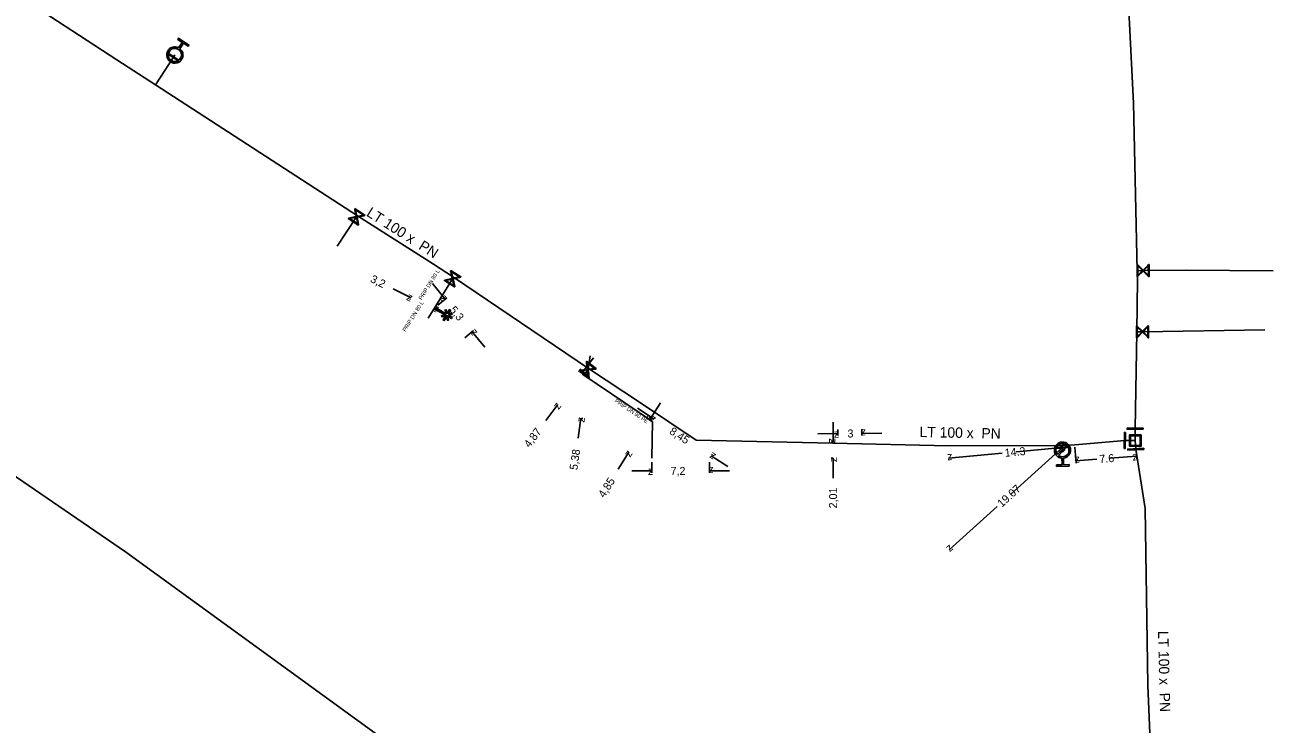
# Model space of a CAD drawing. Extents: x -643544 to -637295, y -1119190 to -1111715.
# Drawn here: x -641787.1 to -641631.1, y -1115673.3 to -1115585.9 of the extents above; entities that cross this region are included whole.
import ezdxf

# ---------------------------------------------------------------- set-up
doc = ezdxf.new("R2010")
doc.units = 0
for name, color, linetype in [('Default', 7, 'Continuous'), ('VP Hydrant', 7, 'Continuous'), ('VP Kótování', 7, 'Continuous'), ('VP Popis přípojky', 7, 'Continuous'), ('VP Přípojka', 7, 'Continuous'), ('VP Změna materiálu', 7, 'Continuous'), ('VP Řad', 7, 'Continuous'), ('VP Řad - popis', 7, 'Continuous'), ('VP Šachta', 7, 'Continuous'), ('VP Šoupě', 7, 'Continuous')]:
    doc.layers.add(name, color=color, linetype=linetype)

msp = doc.modelspace()

# ---------------------------------------------------------------- linework, layer by layer
at = {"layer": 'Default'}
for points in [[(-641767.77, -1115588.87), (-641767.48, -1115589.09), (-641767.41, -1115589.45), (-641767.33, -1115589.85), (-641767.56, -1115590.2), (-641767.78, -1115590.55), (-641768.19, -1115590.63), (-641768.59, -1115590.71), (-641768.94, -1115590.48), (-641769.29, -1115590.26), (-641769.37, -1115589.85), (-641769.45, -1115589.45), (-641769.23, -1115589.1), (-641769, -1115588.75), (-641768.59, -1115588.67), (-641768.23, -1115588.59), (-641767.92, -1115588.77)], [(-641767.94, -1115588.97), (-641768.23, -1115588.78), (-641768.55, -1115588.85), (-641768.88, -1115588.92), (-641769.07, -1115589.2), (-641769.25, -1115589.48), (-641769.19, -1115589.81), (-641769.12, -1115590.14), (-641768.84, -1115590.33), (-641768.56, -1115590.51), (-641768.23, -1115590.44), (-641767.9, -1115590.38), (-641767.71, -1115590.09), (-641767.53, -1115589.81), (-641767.59, -1115589.48), (-641767.66, -1115589.15), (-641767.94, -1115588.97)], [(-641657.52, -1115640.05), (-641657.88, -1115640.04), (-641658.14, -1115639.78), (-641658.44, -1115639.5), (-641658.45, -1115639.08), (-641658.46, -1115638.67), (-641658.18, -1115638.37), (-641657.89, -1115638.07), (-641657.48, -1115638.06), (-641657.07, -1115638.05), (-641656.76, -1115638.33), (-641656.46, -1115638.61), (-641656.45, -1115639.03), (-641656.44, -1115639.44), (-641656.72, -1115639.74), (-641656.98, -1115640.01), (-641657.33, -1115640.05)], [(-641656.96, -1115638.41), (-641657.18, -1115638.24), (-641657.47, -1115638.25), (-641657.81, -1115638.26), (-641658.04, -1115638.5), (-641658.27, -1115638.74), (-641658.26, -1115639.08), (-641658.25, -1115639.37), (-641658.08, -1115639.58)], [(-641657.94, -1115639.71), (-641657.72, -1115639.88), (-641657.43, -1115639.87), (-641657.09, -1115639.86), (-641656.86, -1115639.62), (-641656.63, -1115639.37), (-641656.64, -1115639.04), (-641656.65, -1115638.74), (-641656.83, -1115638.53)]]:
    msp.add_open_spline(points, degree=3, dxfattribs=at)
at = {"layer": 'VP Hydrant'}
for points in [[(-641767.92, -1115588.77), (-641767.47, -1115588.08), (-641768.04, -1115587.7), (-641767.94, -1115587.55), (-641766.64, -1115588.41), (-641766.74, -1115588.56), (-641767.31, -1115588.18), (-641767.77, -1115588.87)], [(-641658.08, -1115639.58), (-641656.96, -1115638.41)], [(-641656.83, -1115638.53), (-641657.94, -1115639.71)], [(-641657.33, -1115640.05), (-641657.31, -1115640.87), (-641656.62, -1115640.85), (-641656.62, -1115641.04), (-641658.18, -1115641.08), (-641658.18, -1115640.89), (-641657.5, -1115640.87), (-641657.52, -1115640.05)]]:
    msp.add_lwpolyline(points, dxfattribs=at)
at = {"layer": 'VP Kótování'}
for points in [[(-641741.11, -1115618.88), (-641738.87, -1115620)], [(-641736.19, -1115618.23), (-641734.61, -1115620.16)], [(-641738.99, -1115620.25), (-641738.98, -1115620.22)], [(-641735.52, -1115620.91), (-641734.41, -1115620)], [(-641736.13, -1115621.67), (-641736.11, -1115621.64)], [(-641733.76, -1115622.53), (-641736, -1115621.42)], [(-641732.16, -1115625.01), (-641731.05, -1115624.1)], [(-641729.66, -1115626.19), (-641731.25, -1115624.26)], [(-641716.05, -1115627.49), (-641717.56, -1115629.47)], [(-641716.48, -1115627.27), (-641716.85, -1115629.75)], [(-641717.69, -1115629.38), (-641717.76, -1115629.32)], [(-641716.8, -1115629.76), (-641716.6, -1115629.78)], [(-641722.04, -1115635.33), (-641720.52, -1115633.35)], [(-641720.64, -1115633.25), (-641720.72, -1115633.19)], [(-641710.58, -1115633.82), (-641708.47, -1115635.18)], [(-641707.7, -1115633.13), (-641709.04, -1115635.23)], [(-641718, -1115637.54), (-641717.64, -1115635.07)], [(-641717.58, -1115635.08), (-641717.39, -1115635.11)], [(-641709.09, -1115635.2), (-641709.25, -1115635.1)], [(-641708.39, -1115635.05), (-641708.34, -1115634.97)], [(-641686.12, -1115635.55), (-641686.12, -1115638.05)], [(-641688.02, -1115637.01), (-641685.52, -1115636.98)], [(-641685.52, -1115636.45), (-641685.52, -1115637.23)], [(-641682.52, -1115636.42), (-641682.52, -1115637.2)], [(-641680.02, -1115636.92), (-641682.52, -1115636.95)], [(-641711.69, -1115639.29), (-641711.86, -1115639.19)], [(-641686.11, -1115638.05), (-641686.37, -1115638.05)], [(-641663.94, -1115644.58), (-641657.46, -1115638.72)], [(-641663.23, -1115639.26), (-641657.46, -1115638.72)], [(-641655.9, -1115638.69), (-641655.75, -1115640.67)], [(-641648.32, -1115638.14), (-641648.17, -1115640.12)], [(-641712.99, -1115641.43), (-641711.65, -1115639.32)], [(-641708.76, -1115640.55), (-641708.76, -1115641.9)], [(-641701.56, -1115640.55), (-641701.56, -1115641.9)], [(-641699.27, -1115641.11), (-641701.37, -1115639.75)], [(-641701.29, -1115639.63), (-641701.24, -1115639.54)], [(-641686.11, -1115640.06), (-641686.37, -1115640.06)], [(-641686.12, -1115642.56), (-641686.12, -1115640.06)], [(-641664.97, -1115639.42), (-641671.7, -1115640.05)], [(-641653.14, -1115640.18), (-641655.77, -1115640.37)], [(-641651.54, -1115640.06), (-641648.2, -1115639.82)], [(-641711.26, -1115641.65), (-641708.76, -1115641.65)], [(-641699.06, -1115641.65), (-641701.56, -1115641.65)], [(-641665.6, -1115646.09), (-641671.6, -1115651.52)]]:
    msp.add_lwpolyline(points, dxfattribs=at)
at = {"layer": 'VP Přípojka'}
for points in [[(-641768.39, -1115589.65), (-641768.56, -1115589.91), (-641770.82, -1115593.36)], [(-641745.58, -1115609.75), (-641745.67, -1115609.88), (-641748.11, -1115613.54)], [(-641648.09, -1115616.63), (-641647.37, -1115616.61), (-641641.99, -1115616.57), (-641631.13, -1115616.63)], [(-641733.55, -1115617.43), (-641733.67, -1115617.62), (-641735.9, -1115621.23)], [(-641735.9, -1115621.23), (-641736.73, -1115622.55)], [(-641648.17, -1115624.26), (-641647.44, -1115624.25), (-641632.15, -1115624)], [(-641716.68, -1115628.83), (-641716.79, -1115628.99), (-641717.29, -1115629.68), (-641708.67, -1115635.47), (-641708.76, -1115640.05)], [(-641657.47, -1115638.45), (-641657.46, -1115638.72), (-641657.45, -1115639.06)]]:
    msp.add_lwpolyline(points, dxfattribs=at)
at = {"layer": 'VP Změna materiálu'}
msp.add_lwpolyline([(-641734.2, -1115622.19), (-641733.74, -1115622.48), (-641733.82, -1115622.61), (-641734.28, -1115622.33), (-641734.17, -1115622.79), (-641734.32, -1115622.82), (-641734.43, -1115622.37), (-641734.73, -1115622.86), (-641734.86, -1115622.77), (-641734.56, -1115622.28), (-641735.02, -1115622.39), (-641735.05, -1115622.23), (-641734.6, -1115622.13), (-641735.95, -1115621.29), (-641735.86, -1115621.16), (-641734.52, -1115622), (-641734.62, -1115621.54), (-641734.47, -1115621.5), (-641734.36, -1115621.96), (-641734.05, -1115621.47), (-641733.92, -1115621.55), (-641734.22, -1115622.04), (-641733.77, -1115621.93), (-641733.74, -1115622.08), (-641734.2, -1115622.19)], dxfattribs=at)
at = {"layer": 'VP Řad'}
for points in [[(-641871.27, -1115465.76), (-641871.29, -1115466.89), (-641871.86, -1115491.42), (-641872.29, -1115517.56), (-641871.83, -1115524.02), (-641871.88, -1115526.43), (-641870.59, -1115527.26), (-641853.18, -1115538.38), (-641851.35, -1115539.55), (-641848.82, -1115541.18), (-641832.86, -1115551.46), (-641801.98, -1115572.94), (-641783.08, -1115585.41), (-641775.63, -1115590.24)], [(-641648.86, -1115562.01), (-641648.8, -1115562.26), (-641649.27, -1115571.37), (-641649.62, -1115574.98), (-641648.57, -1115595.69), (-641648.09, -1115616.63), (-641648.07, -1115617.41), (-641648.08, -1115617.72), (-641648.17, -1115624.26), (-641648.36, -1115636.37), (-641648.34, -1115637.84)], [(-641902.6, -1115564.53), (-641899.1, -1115566.8), (-641882.01, -1115577.67), (-641849.47, -1115600.21), (-641828.83, -1115614.09), (-641810.99, -1115626.84), (-641774.58, -1115651.76), (-641660.08, -1115734.95)], [(-641775.63, -1115590.24), (-641770.82, -1115593.36), (-641745.58, -1115609.75), (-641736.08, -1115615.79), (-641733.55, -1115617.43), (-641716.68, -1115628.83), (-641710.07, -1115633.2), (-641703.24, -1115637.79), (-641686.15, -1115638.19), (-641671.71, -1115638.53), (-641657.47, -1115638.45), (-641655.92, -1115638.39), (-641649.65, -1115637.83), (-641648.34, -1115637.84)], [(-641648.34, -1115637.84), (-641648.29, -1115638.93), (-641647.12, -1115646.33), (-641646.76, -1115668.41), (-641645.92, -1115689.51), (-641645.65, -1115703.6), (-641645.64, -1115703.68)]]:
    msp.add_lwpolyline(points, dxfattribs=at)
at = {"layer": 'VP Šachta'}
for points in [[(-641647.63, -1115637.12), (-641647.63, -1115638.57), (-641649.05, -1115638.57), (-641649.05, -1115637.12), (-641647.63, -1115637.12)], [(-641648.93, -1115637.24), (-641648.93, -1115638.45), (-641647.75, -1115638.45), (-641647.75, -1115637.24), (-641648.93, -1115637.24)]]:
    msp.add_lwpolyline(points, dxfattribs=at)
at = {"layer": 'VP Šoupě'}
for points in [[(-641767.96, -1115590.36), (-641769.21, -1115589.54), (-641769.16, -1115589.46), (-641767.91, -1115590.28), (-641767.96, -1115590.36)], [(-641745.88, -1115608.84), (-641744.63, -1115609.67), (-641744.67, -1115609.73), (-641744.79, -1115609.75), (-641745.62, -1115609.91), (-641745.43, -1115610.86), (-641745.46, -1115610.92), (-641746.71, -1115610.09), (-641746.67, -1115610.03), (-641745.72, -1115609.84), (-641745.89, -1115609.02), (-641745.91, -1115608.89), (-641745.88, -1115608.84)], [(-641745.8, -1115609), (-641745.63, -1115609.83), (-641744.81, -1115609.66), (-641745.8, -1115609)], [(-641745.54, -1115610.76), (-641745.7, -1115609.93), (-641746.53, -1115610.1), (-641745.54, -1115610.76)], [(-641733.91, -1115616.59), (-641732.64, -1115617.38), (-641732.67, -1115617.44), (-641732.8, -1115617.46), (-641733.62, -1115617.65), (-641733.39, -1115618.6), (-641733.43, -1115618.65), (-641734.7, -1115617.86), (-641734.67, -1115617.81), (-641733.72, -1115617.59), (-641733.91, -1115616.77), (-641733.95, -1115616.64), (-641733.91, -1115616.59)], [(-641733.83, -1115616.75), (-641733.64, -1115617.57), (-641732.82, -1115617.38), (-641733.83, -1115616.75)], [(-641646.62, -1115615.86), (-641646.62, -1115617.36), (-641646.69, -1115617.36), (-641646.77, -1115617.26), (-641647.37, -1115616.67), (-641648.05, -1115617.36), (-641648.12, -1115617.36), (-641648.12, -1115615.86), (-641648.06, -1115615.86), (-641647.37, -1115616.54), (-641646.78, -1115615.95), (-641646.69, -1115615.86), (-641646.62, -1115615.86)], [(-641648.03, -1115617.21), (-641647.43, -1115616.61), (-641648.03, -1115616.01), (-641648.03, -1115617.21)], [(-641646.72, -1115616.01), (-641647.31, -1115616.61), (-641646.71, -1115617.2), (-641646.72, -1115616.01)], [(-641733.51, -1115618.49), (-641733.7, -1115617.67), (-641734.52, -1115617.86), (-641733.51, -1115618.49)], [(-641646.7, -1115623.49), (-641646.68, -1115624.99), (-641646.74, -1115624.99), (-641646.83, -1115624.9), (-641647.44, -1115624.31), (-641648.11, -1115625.01), (-641648.18, -1115625.01), (-641648.2, -1115623.51), (-641648.14, -1115623.51), (-641647.44, -1115624.19), (-641646.86, -1115623.58), (-641646.77, -1115623.49), (-641646.7, -1115623.49)], [(-641648.09, -1115624.86), (-641647.5, -1115624.25), (-641648.11, -1115623.67), (-641648.09, -1115624.86)], [(-641646.79, -1115623.65), (-641647.38, -1115624.25), (-641646.77, -1115624.83), (-641646.79, -1115623.65)], [(-641716.92, -1115627.93), (-641715.74, -1115628.86), (-641715.78, -1115628.91), (-641715.9, -1115628.92), (-641716.74, -1115629.02), (-641716.62, -1115629.99), (-641716.66, -1115630.04), (-641717.84, -1115629.11), (-641717.8, -1115629.06), (-641716.84, -1115628.95), (-641716.94, -1115628.11), (-641716.96, -1115627.99), (-641716.92, -1115627.93)], [(-641716.85, -1115628.1), (-641716.75, -1115628.94), (-641715.92, -1115628.84), (-641716.85, -1115628.1)], [(-641716.72, -1115629.87), (-641716.83, -1115629.03), (-641717.66, -1115629.14), (-641716.72, -1115629.87)], [(-641649.57, -1115636.83), (-641649.59, -1115638.83), (-641649.72, -1115638.83), (-641649.7, -1115636.83), (-641649.57, -1115636.83)], [(-641647.36, -1115636.41), (-641649.36, -1115636.44), (-641649.36, -1115636.32), (-641647.36, -1115636.29), (-641647.36, -1115636.41)], [(-641656.71, -1115638.71), (-641658.21, -1115638.83), (-641658.21, -1115638.73), (-641656.72, -1115638.62), (-641656.71, -1115638.71)], [(-641647.29, -1115638.95), (-641649.29, -1115639.04), (-641649.29, -1115638.92), (-641647.29, -1115638.82), (-641647.29, -1115638.95)]]:
    msp.add_lwpolyline(points, dxfattribs=at)

# ---------------------------------------------------------------- texts
at = {"layer": 'VP Kótování'}
for s, rotation, p in [('3,2', 333.5565, (-641744.05, -1115617.98)), ('z', 333.5565, (-641739.54, -1115620.22)), ('z', 309.3403, (-641735.31, -1115620.09)), ('z', 153.5565, (-641735.33, -1115621.2)), ('5,3', 309.3403, (-641734.12, -1115621.55)), ('z', 129.3403, (-641730.54, -1115624.33)), ('z', 232.6491, (-641717.66, -1115628.77)), ('z', 261.6035, (-641717.27, -1115629.18)), ('z', 52.6491, (-641720.43, -1115634.05)), ('z', 81.6035, (-641717.21, -1115635.64)), ('z', 237.4867, (-641709.19, -1115634.54)), ('z', 327.1973, (-641709.17, -1115635.33)), ('4,87', 52.6491, (-641724.07, -1115638.82)), ('8,45', 327.1973, (-641706.67, -1115636.94)), ('z', 270, (-641686.62, -1115637.55)), ('z', 0.6687, (-641686.01, -1115637.49)), ('3', 0.6687, (-641684.31, -1115637.47)), ('z', 180.6687, (-641682.02, -1115636.44)), ('5,38', 81.6035, (-641718.09, -1115641.58)), ('z', 57.4867, (-641711.49, -1115640.01)), ('14.3', 5.3283, (-641664.62, -1115639.89)), ('z', 42.15, (-641657.5, -1115639.43)), ('z', 5.3283, (-641657.91, -1115639.27)), ('z', 147.1973, (-641700.68, -1115639.61)), ('z', 90, (-641685.62, -1115640.56)), ('z', 185.3283, (-641671.25, -1115639.51)), ('z', 184.1582, (-641655.31, -1115639.84)), ('7.6', 4.1581, (-641652.8, -1115640.66)), ('z', 4.1581, (-641648.66, -1115640.36)), ('z', 180, (-641701.06, -1115641.15)), ('4,85', 57.4867, (-641714.72, -1115645.08)), ('2,01', 90, (-641685.62, -1115646.33)), ('19.07', 42.15, (-641665.04, -1115646.26)), ('z', 222.15, (-641671.56, -1115650.81))]:
    msp.add_text(s, height=1, rotation=rotation, dxfattribs=at).set_placement(p)
for s, p in [('z', (-641709.26, -1115642.15)), ('7,2', (-641706.43, -1115642.15))]:
    msp.add_text(s, height=1, dxfattribs=at).set_placement(p)
at = {"layer": 'VP Popis přípojky'}
for s, rotation, p in [('PRIP DN 80 L', 58.2046, (-641737.54, -1115620.33)), ('PRIP DN 80 L', 57.9143, (-641739.56, -1115624.28)), ('PRIP DN 90 PE', 326.128, (-641713.48, -1115633.01))]:
    msp.add_text(s, height=0.5, rotation=rotation, dxfattribs=at).set_placement(p)
at = {"layer": 'VP Řad - popis'}
for rotation, p in [(327.5495, (-641744.55, -1115609.69)), (358.7553, (-641675.32, -1115637.41)), (271.4212, (-641645.51, -1115661.66))]:
    msp.add_text('LT 100 x  PN ', height=1.3, rotation=rotation, dxfattribs=at).set_placement(p)

doc.saveas('drawing.dxf')
